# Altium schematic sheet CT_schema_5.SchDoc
size 282 x 169 mm
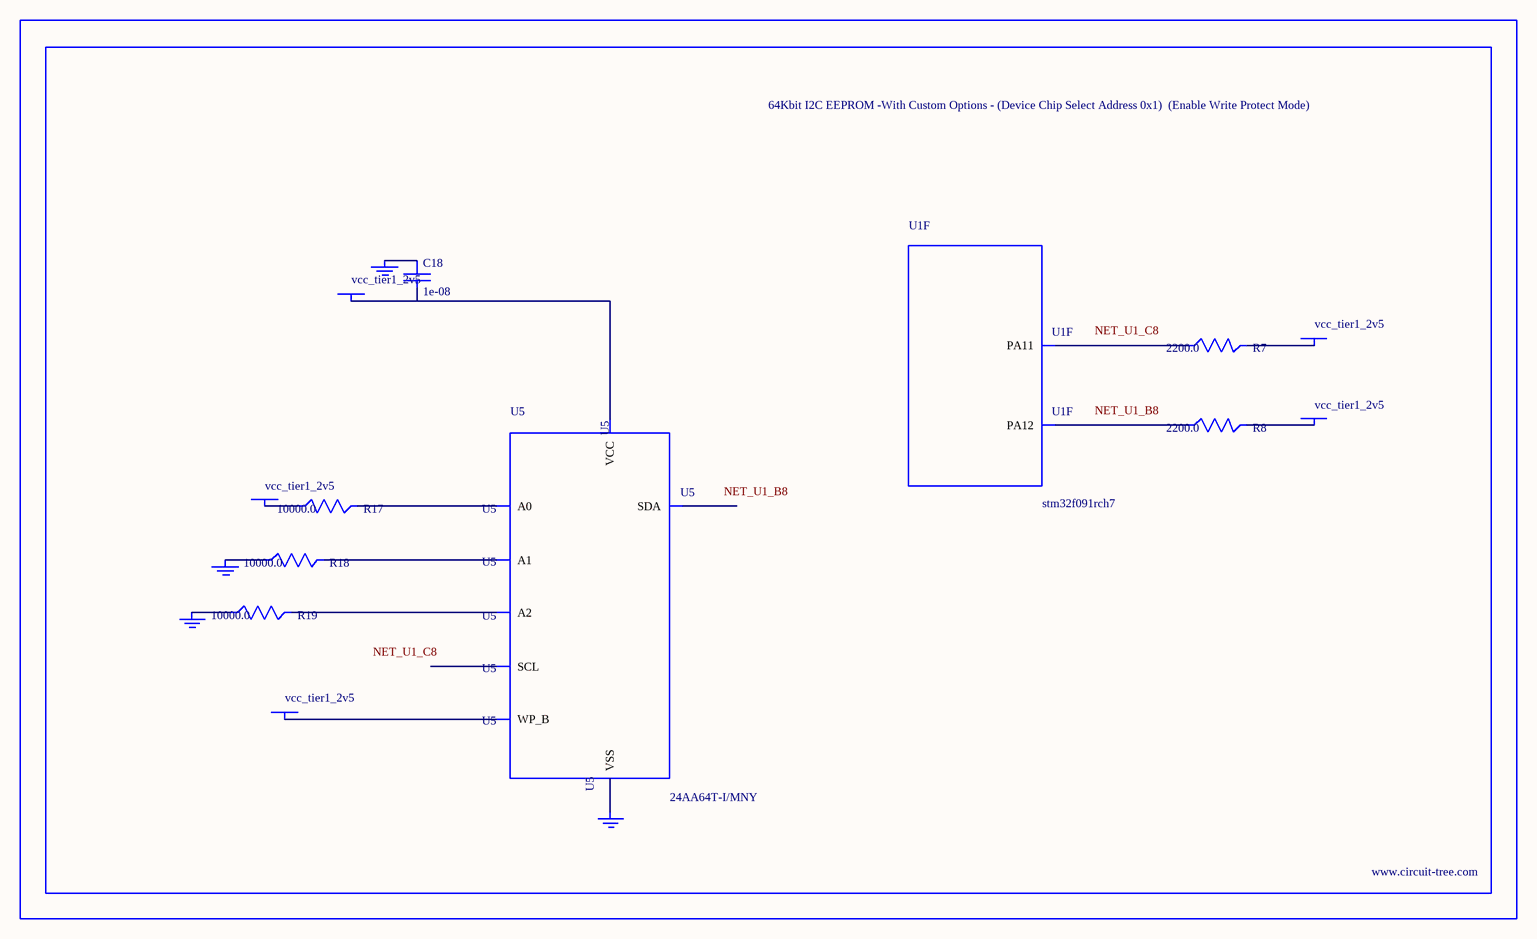
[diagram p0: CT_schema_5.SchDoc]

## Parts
BORDER4  (no value)
C18  1e-08  [C0402]
GND_INSTANCE_4_0  (no value)
GND_INSTANCE_4_1  (no value)
GND_INSTANCE_4_2  (no value)
GND_INSTANCE_4_3  (no value)
POWER_INSTANCE_4_0  vcc_tier1_2v5
POWER_INSTANCE_4_1  vcc_tier1_2v5
POWER_INSTANCE_4_2  vcc_tier1_2v5
POWER_INSTANCE_4_3  vcc_tier1_2v5
POWER_INSTANCE_4_4  vcc_tier1_2v5
R7  2200.0  [R0603]
R8  2200.0  [R0603]
R17  10000.0  [R0603]
R18  10000.0  [R0603]
R19  10000.0  [R0603]
U1  stm32f091rch7  [UFBGA64]  (part F of 6)
U5  24AA64T-I/MNY  [TDFN-8/6MM]

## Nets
NetC18_1: C18.1 GND_INSTANCE_4_2.0(GND)
NetC18_2: C18.2 POWER_INSTANCE_4_2.0(PWR) U5.8(VCC)
NetGND_INSTANCE_4_0_0: GND_INSTANCE_4_0.0(GND) R18.1
NetGND_INSTANCE_4_1_0: GND_INSTANCE_4_1.0(GND) R19.1
NetGND_INSTANCE_4_3_0: GND_INSTANCE_4_3.0(GND) U5.4(VSS)
NetPOWER_INSTANCE_4_0_0: POWER_INSTANCE_4_0.0(PWR) R17.1
NetPOWER_INSTANCE_4_1_0: POWER_INSTANCE_4_1.0(PWR) U5.7(WP_B)
NetPOWER_INSTANCE_4_3_0: POWER_INSTANCE_4_3.0(PWR) R7.2
NetPOWER_INSTANCE_4_4_0: POWER_INSTANCE_4_4.0(PWR) R8.2
NetR7_1: R7.1 U1.C8(PA11)
NetR8_1: R8.1 U1.B8(PA12)
NetR17_2: R17.2 U5.1(A0)
NetR18_2: R18.2 U5.2(A1)
NetR19_2: R19.2 U5.3(A2)

Not connected (* = marked no-connect by the designer): U5 5(SDA) 6(SCL)

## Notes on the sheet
- Labels drawn without touching a wire or pin: NET_U1_B8, NET_U1_C8

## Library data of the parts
BORDER4 = BORDER_PAGE4
C18 = C0402C103K3RAC
GND_INSTANCE_4_0-GND_INSTANCE_4_3 = GND
POWER_INSTANCE_4_0-POWER_INSTANCE_4_4 = PWR
R7 R8 = RC0603JR-072K2L
R17-R19 = RC0603JR-0710KL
